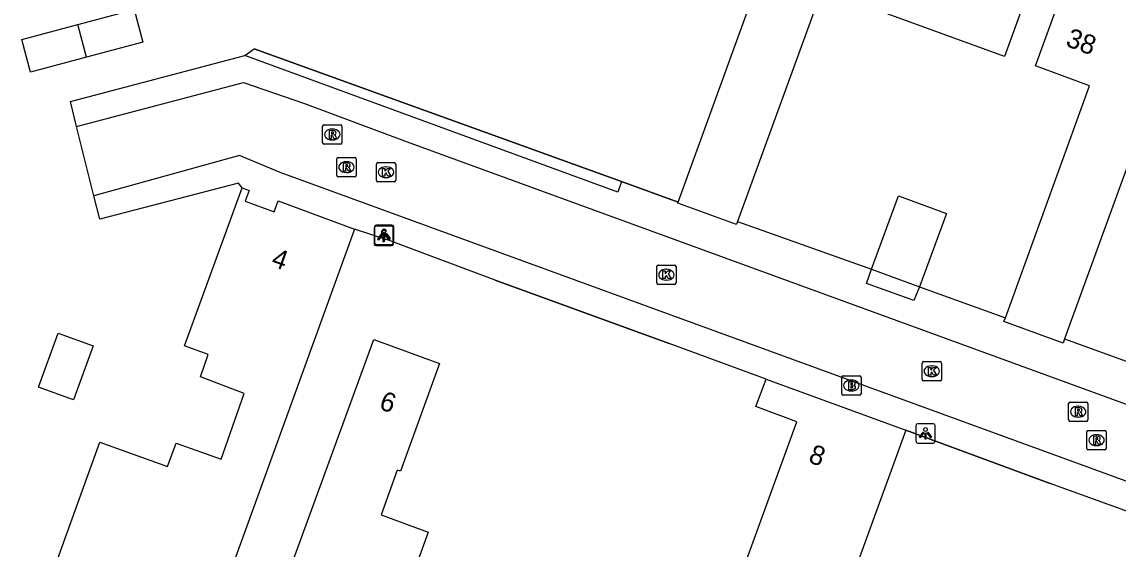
# Model space of a CAD drawing. Extents: x 155275 to 156263, y 382654 to 383635.
# Drawn here: x 155897.7 to 155954.5, y 383087.1 to 383114.4 of the extents above; entities that cross this region are included whole.
import ezdxf

# ---------------------------------------------------------------- set-up
doc = ezdxf.new("R2010")
doc.units = 0
for name, color, linetype in [('IMGEO_Brandkraan', 7, 'Continuous'), ('IMGEO_Haag', 7, 'Continuous'), ('IMGEO_Hek', 7, 'Continuous'), ('IMGEO_Kolk', 7, 'Continuous'), ('IMGEO_Lichtpunt', 7, 'Continuous'), ('IMGEO_Pand', 7, 'Continuous'), ('IMGEO_Pand_nummerreeks', 7, 'Continuous'), ('IMGEO_Rijbaan_lokaal_open', 7, 'Continuous'), ('IMGEO_Rioolput', 7, 'Continuous'), ('IMGEO_Voetpad_open', 7, 'Continuous')]:
    doc.layers.add(name, color=color, linetype=linetype)

msp = doc.modelspace()

# ---------------------------------------------------------------- linework, layer by layer
at = {"layer": 'IMGEO_Brandkraan'}
for p, q in [((155940.137, 383095.14), (155940.137, 383095.992)), ((155940.212, 383096.066), (155941.064, 383096.066)), ((155940.625, 383095.846), (155940.65, 383095.846)), ((155941.138, 383095.992), (155941.138, 383095.14)), ((155941.064, 383095.066), (155940.212, 383095.066)), ((155940.648, 383095.286), (155940.623, 383095.286))]:
    msp.add_line(p, q, dxfattribs=at)
for points in [[(155940.137, 383095.14), (155940.137, 383095.992)], [(155940.212, 383096.066), (155941.064, 383096.066)], [(155940.485, 383095.766), (155940.485, 383095.366), (155940.698, 383095.366)], [(155940.716, 383095.766), (155940.485, 383095.766)], [(155940.664, 383095.685), (155940.61, 383095.685), (155940.61, 383095.609)], [(155940.61, 383095.609), (155940.663, 383095.609)], [(155940.672, 383095.533), (155940.61, 383095.533), (155940.61, 383095.452)], [(155941.138, 383095.992), (155941.138, 383095.14)], [(155941.064, 383095.066), (155940.212, 383095.066)], [(155940.61, 383095.452), (155940.672, 383095.452)]]:
    msp.add_lwpolyline(points, dxfattribs=at)
for centre, radius, start, end in [((155940.214, 383095.99), 0.0765, 91.552, 178.448), ((155940.214, 383095.99), 0.0765, 91.552, 178.448), ((155940.665, 383095.647), 0.0379, 267.8285, 90.9355), ((155940.673, 383095.492), 0.0404, 269.8759, 90.5077), ((155940.72, 383095.621), 0.145, 59.4692, 91.5367), ((155940.745, 383095.668), 0.0922, 285.5137, 58.1501), ((155940.75, 383095.476), 0.105, 301.3115, 78.989), ((155941.062, 383095.99), 0.0765, 1.552, 88.448), ((155941.062, 383095.99), 0.0765, 1.552, 88.448), ((155940.214, 383095.142), 0.0765, 181.552, 268.448), ((155940.214, 383095.142), 0.0765, 181.552, 268.448), ((155940.704, 383095.617), 0.251, 268.6676, 293.5347), ((155941.062, 383095.142), 0.0765, 271.552, 358.448), ((155941.062, 383095.142), 0.0765, 271.552, 358.448)]:
    msp.add_arc(centre, radius, start, end, dxfattribs=at)
for centre, major_axis, ratio, start_param, end_param in [((155940.624, 383095.566), (-0.387, 0.002), 0.722429, 4.712389, 7.853982), ((155940.649, 383095.566), (-0.39, 0.002), 0.717154, 1.570796, 4.712389)]:
    msp.add_ellipse(centre, major_axis=major_axis, ratio=ratio, start_param=start_param, end_param=end_param, dxfattribs=at)
at = {"layer": 'IMGEO_Haag'}
msp.add_lwpolyline([(155909.199, 383112.656), (155909.692, 383113.002), (155928.728, 383106.123)], dxfattribs=at)
at = {"layer": 'IMGEO_Hek'}
for points in [[(155928.728, 383106.123), (155909.692, 383113.002)], [(155931.662, 383105.062), (155928.728, 383106.123)], [(155922.172, 383101.02), (155931.193, 383097.742)], [(155943.454, 383093.254), (155950.932, 383090.494)]]:
    msp.add_lwpolyline(points, dxfattribs=at)
at = {"layer": 'IMGEO_Kolk'}
for p, q in [((155916.02, 383106.179), (155916.02, 383107.031)), ((155916.095, 383107.105), (155916.947, 383107.105)), ((155916.508, 383106.885), (155916.533, 383106.885)), ((155917.021, 383107.031), (155917.021, 383106.179)), ((155916.531, 383106.325), (155916.506, 383106.325)), ((155916.947, 383106.105), (155916.095, 383106.105)), ((155930.626, 383101.803), (155931.478, 383101.803)), ((155930.551, 383100.877), (155930.551, 383101.729)), ((155931.039, 383101.583), (155931.064, 383101.583)), ((155931.552, 383101.729), (155931.552, 383100.877)), ((155931.478, 383100.803), (155930.626, 383100.803)), ((155931.062, 383101.023), (155931.037, 383101.023)), ((155944.305, 383095.88), (155944.305, 383096.732)), ((155944.38, 383096.806), (155945.232, 383096.806)), ((155945.306, 383096.732), (155945.306, 383095.88)), ((155944.793, 383096.586), (155944.818, 383096.586)), ((155945.232, 383095.806), (155944.38, 383095.806)), ((155944.816, 383096.026), (155944.791, 383096.026))]:
    msp.add_line(p, q, dxfattribs=at)
for points in [[(155916.02, 383106.179), (155916.02, 383107.031)], [(155916.095, 383107.105), (155916.947, 383107.105)], [(155917.021, 383107.031), (155917.021, 383106.179)], [(155916.341, 383106.805), (155916.464, 383106.805), (155916.464, 383106.654), (155916.594, 383106.805), (155916.758, 383106.805), (155916.612, 383106.654), (155916.765, 383106.405), (155916.613, 383106.405), (155916.528, 383106.569), (155916.464, 383106.502), (155916.464, 383106.405), (155916.341, 383106.405), (155916.341, 383106.805)], [(155916.947, 383106.105), (155916.095, 383106.105)], [(155930.626, 383101.803), (155931.478, 383101.803)], [(155930.551, 383100.877), (155930.551, 383101.729)], [(155930.872, 383101.503), (155930.995, 383101.503), (155930.995, 383101.352), (155931.125, 383101.503), (155931.289, 383101.503), (155931.143, 383101.352), (155931.296, 383101.103), (155931.144, 383101.103), (155931.059, 383101.267), (155930.995, 383101.2), (155930.995, 383101.103), (155930.872, 383101.103), (155930.872, 383101.503)], [(155931.552, 383101.729), (155931.552, 383100.877)], [(155931.478, 383100.803), (155930.626, 383100.803)], [(155944.305, 383095.88), (155944.305, 383096.732)], [(155944.38, 383096.806), (155945.232, 383096.806)], [(155945.306, 383096.732), (155945.306, 383095.88)], [(155944.626, 383096.506), (155944.749, 383096.506), (155944.749, 383096.355), (155944.879, 383096.506), (155945.043, 383096.506), (155944.897, 383096.355), (155945.05, 383096.106), (155944.898, 383096.106), (155944.813, 383096.27), (155944.749, 383096.203), (155944.749, 383096.106), (155944.626, 383096.106), (155944.626, 383096.506)], [(155945.232, 383095.806), (155944.38, 383095.806)]]:
    msp.add_lwpolyline(points, dxfattribs=at)
for centre, start, end in [((155916.097, 383107.029), 91.552, 178.448), ((155916.097, 383107.029), 91.552, 178.448), ((155916.945, 383107.029), 1.552, 88.448), ((155916.945, 383107.029), 1.552, 88.448), ((155916.097, 383106.181), 181.552, 268.448), ((155916.097, 383106.181), 181.552, 268.448), ((155916.945, 383106.181), 271.552, 358.448), ((155916.945, 383106.181), 271.552, 358.448), ((155930.628, 383101.727), 91.552, 178.448), ((155930.628, 383101.727), 91.552, 178.448), ((155931.476, 383101.727), 1.552, 88.448), ((155931.476, 383101.727), 1.552, 88.448), ((155930.628, 383100.879), 181.552, 268.448), ((155930.628, 383100.879), 181.552, 268.448), ((155931.476, 383100.879), 271.552, 358.448), ((155931.476, 383100.879), 271.552, 358.448), ((155944.382, 383096.73), 91.552, 178.448), ((155944.382, 383096.73), 91.552, 178.448), ((155945.23, 383096.73), 1.552, 88.448), ((155945.23, 383096.73), 1.552, 88.448), ((155944.382, 383095.882), 181.552, 268.448), ((155944.382, 383095.882), 181.552, 268.448), ((155945.23, 383095.882), 271.552, 358.448), ((155945.23, 383095.882), 271.552, 358.448)]:
    msp.add_arc(centre, 0.0765, start, end, dxfattribs=at)
for centre, major_axis, ratio, start_param, end_param in [((155916.507, 383106.605), (-0.387, 0.002), 0.722429, 4.712389, 7.853982), ((155916.532, 383106.605), (-0.39, 0.002), 0.717154, 1.570796, 4.712389), ((155931.038, 383101.303), (-0.387, 0.002), 0.722429, 4.712389, 7.853982), ((155931.063, 383101.303), (-0.39, 0.002), 0.717154, 1.570796, 4.712389), ((155944.792, 383096.306), (-0.387, 0.002), 0.722429, 4.712389, 7.853982), ((155944.817, 383096.306), (-0.39, 0.002), 0.717154, 1.570796, 4.712389)]:
    msp.add_ellipse(centre, major_axis=major_axis, ratio=ratio, start_param=start_param, end_param=end_param, dxfattribs=at)
at = {"layer": 'IMGEO_Lichtpunt'}
for p, q in [((155915.903, 383103.712), (155915.903, 383102.905)), ((155915.903, 383103.712), (155915.903, 383102.905)), ((155915.926, 383103.775), (155915.926, 383102.968)), ((155915.926, 383103.775), (155915.926, 383102.968)), ((155916.805, 383103.807), (155915.997, 383103.807)), ((155916.805, 383103.807), (155915.997, 383103.807)), ((155916.828, 383103.87), (155916.02, 383103.87)), ((155916.828, 383103.87), (155916.02, 383103.87)), ((155916.899, 383102.905), (155916.899, 383103.712)), ((155916.899, 383102.905), (155916.899, 383103.712)), ((155916.922, 383102.968), (155916.922, 383103.775)), ((155916.922, 383102.968), (155916.922, 383103.775)), ((155915.997, 383102.811), (155916.805, 383102.811)), ((155915.997, 383102.811), (155916.805, 383102.811)), ((155916.02, 383102.874), (155916.828, 383102.874)), ((155916.02, 383102.874), (155916.828, 383102.874)), ((155943.982, 383093.491), (155943.982, 383092.684)), ((155943.982, 383093.491), (155943.982, 383092.684)), ((155944.884, 383093.586), (155944.076, 383093.586)), ((155944.884, 383093.586), (155944.076, 383093.586)), ((155944.978, 383092.684), (155944.978, 383093.491)), ((155944.978, 383092.684), (155944.978, 383093.491)), ((155944.076, 383092.59), (155944.884, 383092.59)), ((155944.076, 383092.59), (155944.884, 383092.59))]:
    msp.add_line(p, q, dxfattribs=at)
for points in [[(155916.277, 383103.376), (155916.316, 383103.348), (155916.128, 383103.086), (155916.09, 383103.113), (155916.277, 383103.376)], [(155916.3, 383103.439), (155916.339, 383103.411), (155916.151, 383103.149), (155916.113, 383103.176), (155916.3, 383103.439)], [(155916.379, 383103.328), (155916.426, 383103.328), (155916.426, 383103.006), (155916.379, 383103.006), (155916.379, 383103.328)], [(155916.402, 383103.391), (155916.449, 383103.391), (155916.449, 383103.069), (155916.402, 383103.069), (155916.402, 383103.391)], [(155916.489, 383103.348), (155916.527, 383103.375), (155916.714, 383103.113), (155916.675, 383103.085), (155916.489, 383103.348)], [(155916.512, 383103.411), (155916.55, 383103.438), (155916.737, 383103.176), (155916.698, 383103.148), (155916.512, 383103.411)], [(155944.356, 383093.155), (155944.395, 383093.127), (155944.207, 383092.865), (155944.169, 383092.892), (155944.356, 383093.155)], [(155944.458, 383093.107), (155944.505, 383093.107), (155944.505, 383092.785), (155944.458, 383092.785), (155944.458, 383093.107)], [(155944.568, 383093.127), (155944.606, 383093.154), (155944.793, 383092.892), (155944.754, 383092.864), (155944.568, 383093.127)]]:
    msp.add_lwpolyline(points, dxfattribs=at)
for centre in [(155916.402, 383103.51), (155916.425, 383103.573), (155944.481, 383093.289)]:
    msp.add_circle(centre, 0.0994, dxfattribs=at)
for centre, start, end in [((155915.997, 383103.712), 90, 180), ((155915.997, 383103.712), 90, 180), ((155916.02, 383103.775), 90, 180), ((155916.02, 383103.775), 90, 180), ((155916.805, 383103.712), 0, 90), ((155916.805, 383103.712), 0, 90), ((155916.828, 383103.775), 0, 90), ((155916.828, 383103.775), 0, 90), ((155915.997, 383102.905), 180, 270), ((155915.997, 383102.905), 180, 270), ((155916.02, 383102.968), 180, 270), ((155916.02, 383102.968), 180, 270), ((155916.805, 383102.905), 270, 0), ((155916.805, 383102.905), 270, 360), ((155916.828, 383102.968), 270, 0), ((155916.828, 383102.968), 270, 360), ((155944.076, 383093.491), 90, 180), ((155944.076, 383093.491), 90, 180), ((155944.884, 383093.491), 0, 90), ((155944.884, 383093.491), 0, 90), ((155944.076, 383092.684), 180, 270), ((155944.076, 383092.684), 180, 270), ((155944.884, 383092.684), 270, 0), ((155944.884, 383092.684), 270, 360)]:
    msp.add_arc(centre, 0.0946, start, end, dxfattribs=at)
at = {"layer": 'IMGEO_Pand'}
for points in [[(155931.662, 383105.062), (155935.744, 383116.297), (155932.921, 383117.318), (155936.856, 383128.137), (155942.731, 383125.992), (155934.74, 383104.05)], [(155946.189, 383124.799), (155952.215, 383122.624), (155948.578, 383112.599), (155942.55, 383114.788), (155946.189, 383124.799)], [(155948.619, 383099.074), (155952.986, 383111.085), (155950.181, 383112.119), (155953.767, 383121.976), (155959.642, 383119.852), (155959.296, 383118.902)], [(155900.557, 383114.251), (155903.464, 383115.022), (155903.911, 383113.338), (155901.005, 383112.566)], [(155901.005, 383112.566), (155898.099, 383111.794), (155897.651, 383113.48), (155900.557, 383114.251)], [(155901.005, 383112.566), (155900.557, 383114.251)], [(155955.885, 383109.498), (155951.685, 383097.975)], [(155914.89, 383103.668), (155907.09, 383082.193), (155905.745, 383082.68), (155904.847, 383080.197), (155898.076, 383082.648), (155901.693, 383092.641), (155905.196, 383091.37), (155905.639, 383092.588), (155907.97, 383091.748), (155909.165, 383095.155), (155906.905, 383096.018), (155907.31, 383097.173), (155906.079, 383097.621), (155909.057, 383105.798)], [(155909.057, 383105.798), (155909.427, 383105.662), (155909.225, 383105.106), (155910.721, 383104.565), (155910.923, 383105.119), (155914.89, 383103.668)], [(155941.683, 383101.583), (155943.077, 383105.38), (155945.567, 383104.465), (155944.173, 383100.668)], [(155934.74, 383104.05), (155934.687, 383103.904), (155931.643, 383105.01), (155931.662, 383105.062)], [(155941.683, 383101.583), (155944.173, 383100.668)], [(155951.685, 383097.975), (155951.609, 383097.767), (155948.547, 383098.877), (155948.619, 383099.074)], [(155900.323, 383094.824), (155898.512, 383095.488), (155899.535, 383098.28), (155901.346, 383097.616), (155900.323, 383094.824)], [(155919.288, 383096.704), (155917.266, 383091.137), (155917.105, 383091.192), (155916.272, 383088.866), (155918.699, 383087.979), (155917.998, 383086.014), (155921.891, 383084.543), (155918.68, 383075.713), (155914.755, 383077.135), (155914.559, 383076.625), (155910.851, 383077.978), (155912.408, 383082.29), (155912.972, 383083.851), (155911, 383084.573), (155915.893, 383097.946), (155919.288, 383096.704)], [(155943.454, 383093.254), (155935.094, 383070.315), (155934.792, 383070.427), (155934.893, 383070.708), (155932.279, 383071.669), (155931.802, 383070.364), (155926.226, 383072.4), (155927.283, 383075.301), (155926.862, 383075.457), (155927.365, 383076.853), (155927.796, 383076.692), (155928.846, 383079.561), (155932.237, 383078.379), (155933.03, 383080.557), (155937.805, 383093.684), (155935.693, 383094.477), (155936.22, 383095.894)], [(155936.22, 383095.894), (155943.454, 383093.254)]]:
    msp.add_lwpolyline(points, dxfattribs=at)
at = {"layer": 'IMGEO_Rijbaan_lokaal_open'}
for points in [[(155900.482, 383108.98), (155909.136, 383111.255), (155912.301, 383110.169), (155917.614, 383108.176), (155988.636, 383082.307)], [(155901.383, 383105.384), (155900.482, 383108.98)], [(155987.356, 383078.784), (155911.031, 383106.591), (155908.922, 383107.475), (155901.383, 383105.384)]]:
    msp.add_lwpolyline(points, dxfattribs=at)
at = {"layer": 'IMGEO_Rioolput'}
for p, q in [((155913.234, 383108.133), (155913.234, 383108.985)), ((155913.309, 383109.059), (155914.161, 383109.059)), ((155913.722, 383108.839), (155913.747, 383108.839)), ((155914.235, 383108.985), (155914.235, 383108.133)), ((155914.161, 383108.059), (155913.309, 383108.059)), ((155913.745, 383108.279), (155913.72, 383108.279)), ((155913.97, 383106.445), (155913.97, 383107.297)), ((155914.045, 383107.371), (155914.897, 383107.371)), ((155914.458, 383107.151), (155914.483, 383107.151)), ((155914.971, 383107.297), (155914.971, 383106.445)), ((155914.897, 383106.371), (155914.045, 383106.371)), ((155914.481, 383106.591), (155914.456, 383106.591)), ((155951.894, 383093.786), (155951.894, 383094.638)), ((155951.969, 383094.712), (155952.821, 383094.712)), ((155952.382, 383094.492), (155952.407, 383094.492)), ((155952.895, 383094.638), (155952.895, 383093.786)), ((155952.405, 383093.932), (155952.38, 383093.932)), ((155952.821, 383093.712), (155951.969, 383093.712)), ((155952.918, 383093.238), (155953.77, 383093.238)), ((155952.843, 383092.312), (155952.843, 383093.164)), ((155953.331, 383093.018), (155953.356, 383093.018)), ((155953.844, 383093.164), (155953.844, 383092.312)), ((155953.77, 383092.238), (155952.918, 383092.238)), ((155953.354, 383092.458), (155953.329, 383092.458))]:
    msp.add_line(p, q, dxfattribs=at)
for points in [[(155913.234, 383108.133), (155913.234, 383108.985)], [(155913.309, 383109.059), (155914.161, 383109.059)], [(155913.823, 383108.757), (155913.571, 383108.759), (155913.571, 383108.359)], [(155913.749, 383108.678), (155913.695, 383108.678), (155913.695, 383108.597)], [(155913.695, 383108.597), (155913.747, 383108.597)], [(155914.235, 383108.985), (155914.235, 383108.133)], [(155914.161, 383108.059), (155913.309, 383108.059)], [(155913.571, 383108.359), (155913.695, 383108.359), (155913.695, 383108.521), (155913.706, 383108.521)], [(155913.753, 383108.492), (155913.824, 383108.359), (155913.964, 383108.359), (155913.899, 383108.485)], [(155913.97, 383106.445), (155913.97, 383107.297)], [(155914.045, 383107.371), (155914.897, 383107.371)], [(155914.559, 383107.069), (155914.307, 383107.071), (155914.307, 383106.671)], [(155914.485, 383106.99), (155914.431, 383106.99), (155914.431, 383106.909)], [(155914.431, 383106.909), (155914.483, 383106.909)], [(155914.971, 383107.297), (155914.971, 383106.445)], [(155914.897, 383106.371), (155914.045, 383106.371)], [(155914.307, 383106.671), (155914.431, 383106.671), (155914.431, 383106.833), (155914.442, 383106.833)], [(155914.489, 383106.804), (155914.56, 383106.671), (155914.7, 383106.671), (155914.635, 383106.797)], [(155951.894, 383093.786), (155951.894, 383094.638)], [(155951.969, 383094.712), (155952.821, 383094.712)], [(155952.483, 383094.41), (155952.231, 383094.412), (155952.231, 383094.012)], [(155952.895, 383094.638), (155952.895, 383093.786)], [(155952.231, 383094.012), (155952.355, 383094.012), (155952.355, 383094.174), (155952.366, 383094.174)], [(155952.409, 383094.331), (155952.355, 383094.331), (155952.355, 383094.25)], [(155952.355, 383094.25), (155952.407, 383094.25)], [(155952.413, 383094.145), (155952.484, 383094.012), (155952.624, 383094.012), (155952.559, 383094.138)], [(155952.821, 383093.712), (155951.969, 383093.712)], [(155952.918, 383093.238), (155953.77, 383093.238)], [(155952.843, 383092.312), (155952.843, 383093.164)], [(155953.432, 383092.936), (155953.18, 383092.938), (155953.18, 383092.538)], [(155953.18, 383092.538), (155953.304, 383092.538), (155953.304, 383092.7), (155953.315, 383092.7)], [(155953.358, 383092.857), (155953.304, 383092.857), (155953.304, 383092.776)], [(155953.304, 383092.776), (155953.356, 383092.776)], [(155953.362, 383092.671), (155953.433, 383092.538), (155953.573, 383092.538), (155953.508, 383092.664)], [(155953.844, 383093.164), (155953.844, 383092.312)], [(155953.77, 383092.238), (155952.918, 383092.238)]]:
    msp.add_lwpolyline(points, dxfattribs=at)
for centre, radius, start, end in [((155913.311, 383108.983), 0.0765, 91.552, 178.448), ((155913.311, 383108.983), 0.0765, 91.552, 178.448), ((155913.731, 383108.786), 0.19, 274.7715, 282.9687), ((155913.755, 383108.582), 0.0964, 77.0061, 93.1865), ((155913.769, 383108.639), 0.0378, 276.6634, 79.6772), ((155913.822, 383108.647), 0.109, 350.3612, 89.416), ((155913.82, 383108.647), 0.112, 277.5842, 350.9817), ((155914.159, 383108.983), 0.0765, 1.552, 88.448), ((155914.159, 383108.983), 0.0765, 1.552, 88.448), ((155913.311, 383108.135), 0.0765, 181.552, 268.448), ((155913.311, 383108.135), 0.0765, 181.552, 268.448), ((155913.705, 383108.468), 0.0533, 26.0293, 88.6989), ((155913.804, 383108.432), 0.108, 29.5134, 73.7905), ((155914.159, 383108.135), 0.0765, 271.552, 358.448), ((155914.159, 383108.135), 0.0765, 271.552, 358.448), ((155914.047, 383107.295), 0.0765, 91.552, 178.448), ((155914.047, 383107.295), 0.0765, 91.552, 178.448), ((155914.467, 383107.098), 0.19, 274.7715, 282.9687), ((155914.491, 383106.894), 0.0964, 77.0061, 93.1865), ((155914.505, 383106.951), 0.0378, 276.6634, 79.6772), ((155914.558, 383106.959), 0.109, 350.3612, 89.416), ((155914.556, 383106.959), 0.112, 277.5842, 350.9817), ((155914.895, 383107.295), 0.0765, 1.552, 88.448), ((155914.895, 383107.295), 0.0765, 1.552, 88.448), ((155914.047, 383106.447), 0.0765, 181.552, 268.448), ((155914.047, 383106.447), 0.0765, 181.552, 268.448), ((155914.441, 383106.78), 0.0533, 26.0293, 88.6989), ((155914.54, 383106.744), 0.108, 29.5134, 73.7905), ((155914.895, 383106.447), 0.0765, 271.552, 358.448), ((155914.895, 383106.447), 0.0765, 271.552, 358.448), ((155951.971, 383094.636), 0.0765, 91.552, 178.448), ((155951.971, 383094.636), 0.0765, 91.552, 178.448), ((155952.482, 383094.3), 0.109, 350.3612, 89.416), ((155952.819, 383094.636), 0.0765, 1.552, 88.448), ((155952.819, 383094.636), 0.0765, 1.552, 88.448), ((155952.365, 383094.121), 0.0533, 26.0293, 88.6989), ((155952.391, 383094.439), 0.19, 274.7715, 282.9687), ((155952.415, 383094.235), 0.0964, 77.0061, 93.1865), ((155952.429, 383094.292), 0.0378, 276.6634, 79.6772), ((155952.48, 383094.3), 0.112, 277.5842, 350.9817), ((155952.464, 383094.085), 0.108, 29.5134, 73.7905), ((155951.971, 383093.788), 0.0765, 181.552, 268.448), ((155951.971, 383093.788), 0.0765, 181.552, 268.448), ((155952.819, 383093.788), 0.0765, 271.552, 358.448), ((155952.819, 383093.788), 0.0765, 271.552, 358.448), ((155952.92, 383093.162), 0.0765, 91.552, 178.448), ((155952.92, 383093.162), 0.0765, 91.552, 178.448), ((155953.768, 383093.162), 0.0765, 1.552, 88.448), ((155953.768, 383093.162), 0.0765, 1.552, 88.448), ((155953.314, 383092.647), 0.0533, 26.0293, 88.6989), ((155953.34, 383092.965), 0.19, 274.7715, 282.9687), ((155953.364, 383092.761), 0.0964, 77.0061, 93.1865), ((155953.378, 383092.818), 0.0378, 276.6634, 79.6772), ((155953.431, 383092.826), 0.109, 350.3612, 89.416), ((155953.429, 383092.826), 0.112, 277.5842, 350.9817), ((155953.413, 383092.611), 0.108, 29.5134, 73.7905), ((155952.92, 383092.314), 0.0765, 181.552, 268.448), ((155952.92, 383092.314), 0.0765, 181.552, 268.448), ((155953.768, 383092.314), 0.0765, 271.552, 358.448), ((155953.768, 383092.314), 0.0765, 271.552, 358.448)]:
    msp.add_arc(centre, radius, start, end, dxfattribs=at)
for centre, major_axis, ratio, start_param, end_param in [((155913.721, 383108.559), (-0.387, 0.002), 0.722429, 4.712389, 7.853982), ((155913.746, 383108.559), (-0.39, 0.002), 0.717154, 1.570796, 4.712389), ((155914.457, 383106.871), (-0.387, 0.002), 0.722429, 4.712389, 7.853982), ((155914.482, 383106.871), (-0.39, 0.002), 0.717154, 1.570796, 4.712389), ((155952.381, 383094.212), (-0.387, 0.002), 0.722429, 4.712389, 7.853982), ((155952.406, 383094.212), (-0.39, 0.002), 0.717154, 1.570796, 4.712389), ((155953.33, 383092.738), (-0.387, 0.002), 0.722429, 4.712389, 7.853982), ((155953.355, 383092.738), (-0.39, 0.002), 0.717154, 1.570796, 4.712389)]:
    msp.add_ellipse(centre, major_axis=major_axis, ratio=ratio, start_param=start_param, end_param=end_param, dxfattribs=at)
at = {"layer": 'IMGEO_Voetpad_open'}
for points in [[(155900.482, 383108.98), (155900.161, 383110.26), (155909.199, 383112.656)], [(155928.728, 383106.123), (155928.526, 383105.571), (155917.867, 383109.467), (155909.199, 383112.656)], [(155909.057, 383105.798), (155908.868, 383106.034), (155901.686, 383104.174), (155901.383, 383105.384)], [(155928.728, 383106.123), (155931.662, 383105.062)], [(155934.74, 383104.05), (155941.683, 383101.583)], [(155936.22, 383095.894), (155931.193, 383097.742), (155922.172, 383101.02), (155916.729, 383103.059), (155914.89, 383103.668)], [(155944.173, 383100.668), (155943.88, 383099.975), (155941.43, 383100.846), (155941.683, 383101.583)], [(155944.173, 383100.668), (155948.619, 383099.074)], [(155951.685, 383097.975), (155954.883, 383096.828)], [(155959.483, 383087.406), (155950.932, 383090.494), (155943.454, 383093.254)]]:
    msp.add_lwpolyline(points, dxfattribs=at)

# ---------------------------------------------------------------- texts
at = {"layer": 'IMGEO_Pand_nummerreeks'}
for s, rotation, p in [('38', 339.7647, (155951.692, 383113.161)), ('4', 339.907, (155910.515, 383101.775)), ('6', 339.9034, (155916.109, 383094.374)), ('8', 340.0665, (155938.359, 383091.613))]:
    msp.add_text(s, height=1, rotation=rotation, dxfattribs=at).set_placement(p)

doc.saveas('drawing.dxf')
